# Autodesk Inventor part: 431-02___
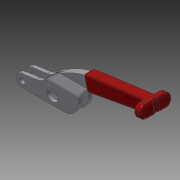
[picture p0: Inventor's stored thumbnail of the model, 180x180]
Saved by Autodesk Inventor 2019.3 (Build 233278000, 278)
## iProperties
Created: 2010-06
Part Number: 431-02___
Material: Ogólny
Document SubType Name: Modeling
Designer: CADENGINEERING4
Density: 1 g/cm^3
Appearance: Domyślna
Author: CADENGINEERING4
Revision Number: ANY
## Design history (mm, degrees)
feature "NONE"
node "Bryła1"
